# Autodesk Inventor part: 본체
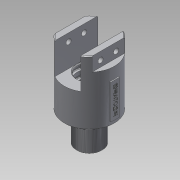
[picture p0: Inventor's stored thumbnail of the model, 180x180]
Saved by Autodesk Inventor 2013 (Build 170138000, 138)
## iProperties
Created: 2019-02
Part Number: 본체
Material: 알루미늄 6061
Document SubType Name: Modeling
Designer: Administrator
Density: 2.71 g/cm^3
Mass: 347.292 g
Surface Area: 290.929 cm^2
Volume: 128.152 cm^3
Author: Administrator
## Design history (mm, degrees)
sketch "스케치1"
  geometry: C1 r 29 at (0, 0); 1 further point
  constraints: 1 centre point, 1 coincident
  dimensions: "d0" = 58 diameter of C1
extrude "돌출1" new body sketch "스케치1" distance "d1" = 74; taper "d2" = 0 deg
sketch "스케치2"
  geometry: C1 r 29 at (0, 0) reference; C2 r 13 at (0, 0)
  constraints: 1 centre point, 1 coincident
  dimensions: "d3" = 26 diameter of C2
extrude "돌출2" join sketch "스케치2" distance "d4" = 5; taper "d5" = 0 deg
sketch "스케치3"
  geometry: C1 r 13 at (0, 0) reference; C2 r 15 at (0, 0)
  constraints: 1 centre point, 1 coincident
  dimensions: "d6" = 30 diameter of C2
extrude "돌출3" join sketch "스케치3" distance "d7" = 29; taper "d8" = 0 deg
feature "스레드1" dims "d9" = 10, "d10" = 0
sketch "스케치4"
  geometry: L1 (-15, 61.329)-(15, 61.329); L2 (15, 61.329)-(15, -63.987); L3 (15, -63.987)-(-15, -63.987); L4 (-15, -63.987)-(-15, 61.329); C1 r 29 at (0, 0) reference; 1 further point
  constraints: 8 end point, 2 parallel, 1 horizontal, 1 midpoint, 1 perpendicular, 1 vertical alignment
  dimensions: "d11" = 30 distance of L1.start L1.end
extrude "돌출4" cut sketch "스케치4" distance "d13" = 36; taper "d14" = 0 deg
sketch "스케치5"
  geometry: L1 (15, 24.819)-(15, -24.819) reference; L2 (22, 31.355)-(35.093, 31.355); L3 (35.093, 31.355)-(35.093, -38.476); L4 (35.093, -38.476)-(22, -38.476); L5 (22, -38.476)-(22, 31.355)
  constraints: 8 end point, 2 parallel, 1 horizontal, 1 perpendicular
  dimensions: "d15" = 7 distance between parallel lines of L5 L1; "d16" = 13.09341 distance of L2.start L2.end; "d17" = 69.83151 distance of L2.end L3.end
extrude "돌출5" cut sketch "스케치5" distance "d18" = 16; taper "d19" = 0 deg
sketch "스케치6"
  geometry: L1 (0, 0)-(0, 37.789) reference; C1 r 3 at (9, 27.894); C2 r 3 at (9, 9.894); 1 further point
  constraints: 2 centre point, 1 vertical alignment
  dimensions: "d20" = 6 diameter of C1; "d21" = 6 diameter of C2; "d22" = 18 distance of C1.centre C2.centre; "d23" = 9 horizontal distance of C2.centre L1.start; "d26" = 9 vertical distance of point (74, 18.894) C2.centre
extrude "돌출6" cut sketch "스케치6" stored distance "d27" = 16; taper "d28" = 0 deg
sketch "스케치7"
  geometry: C1 r 14 at (0, 0); A1 r 29 centre (0, 0) between (15, 24.819) and (-15, 24.819) reference
  constraints: 1 centre point, 1 coincident
  dimensions: "d29" = 28 diameter of C1
extrude "돌출7" cut sketch "스케치7" distance "d30" = 27; taper "d31" = 0 deg
sketch "스케치8"
  geometry: L1 (17, 35.35)-(14, 35.35); L2 (14, 35.35)-(14, 30.65); L3 (14, 30.65)-(17, 30.65); L4 (17, 30.65)-(17, 35.35); L5 (-24.819, 38)-(24.819, 38) reference; L6 (14, 38)-(14, 11) reference; L7 (17, 26.35)-(14, 26.35); L8 (14, 26.35)-(14, 21.65); L9 (14, 21.65)-(17, 21.65); L10 (17, 21.65)-(17, 26.35); L11 (14, 11)-(16, 11); L12 (16, 11)-(16, 18); L13 (16, 18)-(14, 18); L14 (14, 18)-(14, 11); L15 (-14, 38)-(-14, 11) reference; L16 (0, -55.6)-(0, 95.6) reference; 3 further points
  constraints: 24 end point, 6 parallel, 3 horizontal, 3 perpendicular, 2 midpoint, 2 point on line
  dimensions: "d32" = 3 distance of L3.end L2.end; "d33" = 4.7 distance of L2.end L1.end; "d34" = 5 distance from line of point (17, 33) L5; "d37" = 3 distance of L9.end L8.end; "d38" = 4.7 distance of L8.end L7.end; "d39" = 9 distance of point (17, 24) point (17, 33); "d40" = 2 distance of L13.end L12.end; "d41" = 7 distance of L12.end L11.end
revolve "회전1" sketch "스케치8" stored, may be unused: angle "d42" = 90 deg
node "작업 평면1"
sketch "스케치9"
  geometry: L1 (5, 45)-(-5, 45); L2 (-5, 45)-(-5, 5); L3 (-5, 5)-(5, 5); L4 (5, 5)-(5, 45); 2 further points
  constraints: 8 end point, 2 parallel, 1 horizontal, 1 midpoint, 1 perpendicular, 1 vertical alignment
  dimensions: "d44" = 10 distance of L3.end L2.end; "d45" = 40 distance of L2.end L1.end; "d46" = 5 distance from line of point (0, 0) L3
extrude "돌출8" join sketch "스케치9" stored distance "d47" = 27; taper "d48" = 0 deg
sketch "스케치10"
  geometry: L1 (-45, 5)-(-45, -5) reference; L2 (-5, 5)-(-45, 5) reference; 2 further points
  constraints: 1 other
  dimensions: "d49" = 5 distance from line of L2 point (-25, 0); "d50" = 20 distance from line of point (-25, 0) L1
feature "엠보싱1" sketch "스케치10" dims "d11" = 30, "d51" = 0.5, "d52" = 0
hole "구멍1" diameter "d55" = 12.376; stored, may be unused: countersink angle "d59" = 90 deg, drill point angle "d61" = 118 deg; dims "d53" = 10, "d54" = 10, "d56" = 18, "d57" = 4, "d58" = 2, "d60" = 22
sketch "스케치12"
  geometry: C1 r 16 at (0, 0) reference; C2 r 4 at (0, 0)
  constraints: 1 centre point, 1 coincident
  dimensions: "d62" = 8 diameter of C2
extrude "돌출9" cut sketch "스케치12" stored distance "d63" = 0; taper "d64" = 0 deg
chamfer "모따기1" distance "d65" = 1; stored, may be unused: second distance "d66" = 2, angle "d67" = 45 deg
fillet "모깎기1" dims "d68" = 0.8
chamfer "모따기2" distance "d69" = 1; stored, may be unused: second distance "d70" = 2, angle "d71" = 45 deg
node "솔리드1"
mirror "대칭1"
